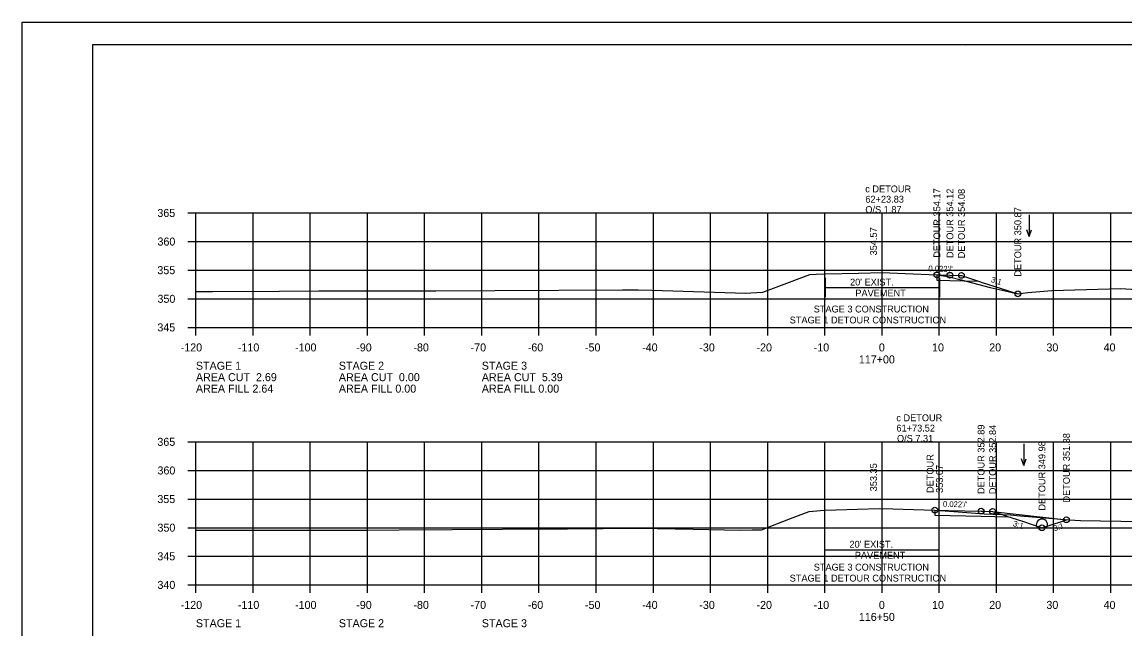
# Model space of a CAD drawing. Extents: x 1630712 to 1632516, y 782146 to 785403.
# Drawn here: x 1632182.6 to 1632375.4, y 785297.3 to 785403.3 of the extents above; entities that cross this region are included whole.
import ezdxf

# ---------------------------------------------------------------- set-up
doc = ezdxf.new("R2010")
doc.units = 0
for name, color, linetype in [('Default', 7, 'Continuous'), ('Notes', 7, 'Continuous'), ('R_Axis', 7, 'Continuous'), ('R_Axis Annot', 7, 'Continuous'), ('R_Border', 7, 'Continuous'), ('R_Detour Subgrade', 7, 'Continuous'), ('R_Detour Surface', 7, 'Continuous'), ('R_Exist Surface', 7, 'Continuous'), ('R_Grid', 7, 'Continuous'), ('R_No Plot', 7, 'Continuous'), ('R_Water Annot', 7, 'Continuous'), ('R_Xsect Elev', 7, 'Continuous'), ('R_Xsect Elev Detour', 7, 'Continuous'), ('R_Xsect Slope', 7, 'Continuous')]:
    doc.layers.add(name, color=color, linetype=linetype)

msp = doc.modelspace()

# ---------------------------------------------------------------- linework, layer by layer
at = {"layer": 'Default'}
for centre, radius, start, end in [((1632360.92, 785315.48), 0.995, 356.5785, 183.4215), ((1632360.34, 785315.45), 0.412, 183.4215, 256.4158), ((1632360.92, 785317.85), 2.89, 256.4158, 283.5842), ((1632361.5, 785315.45), 0.412, 283.5842, 356.5785)]:
    msp.add_arc(centre, radius, start, end, dxfattribs=at)
at = {"layer": 'Notes'}
for p, q in [((1632323.06, 785355.24), (1632323.06, 785358.64)), ((1632323.06, 785356.94), (1632343.06, 785356.94)), ((1632343.06, 785355.24), (1632343.06, 785358.64)), ((1632322.96, 785309.42), (1632322.96, 785312.82)), ((1632342.96, 785309.42), (1632342.96, 785312.82)), ((1632322.96, 785311.12), (1632342.96, 785311.12))]:
    msp.add_line(p, q, dxfattribs=at)
at = {"layer": 'R_Axis'}
for p, q in [((1632211.56, 785369.98), (1632212.96, 785369.98)), ((1632212.96, 785349.98), (1632212.96, 785369.98)), ((1632211.56, 785364.98), (1632212.96, 785364.98)), ((1632211.56, 785359.98), (1632212.96, 785359.98)), ((1632211.56, 785354.98), (1632212.96, 785354.98)), ((1632211.56, 785349.98), (1632212.96, 785349.98)), ((1632212.96, 785349.98), (1632492.96, 785349.98)), ((1632212.96, 785348.58), (1632212.96, 785349.98)), ((1632222.96, 785348.58), (1632222.96, 785349.98)), ((1632232.96, 785348.58), (1632232.96, 785349.98)), ((1632242.96, 785348.58), (1632242.96, 785349.98)), ((1632252.96, 785348.58), (1632252.96, 785349.98)), ((1632262.96, 785348.58), (1632262.96, 785349.98)), ((1632272.96, 785348.58), (1632272.96, 785349.98)), ((1632282.96, 785348.58), (1632282.96, 785349.98)), ((1632292.96, 785348.58), (1632292.96, 785349.98)), ((1632302.96, 785348.58), (1632302.96, 785349.98)), ((1632312.96, 785348.58), (1632312.96, 785349.98)), ((1632322.96, 785348.58), (1632322.96, 785349.98)), ((1632332.96, 785348.58), (1632332.96, 785349.98)), ((1632342.96, 785348.58), (1632342.96, 785349.98)), ((1632352.96, 785348.58), (1632352.96, 785349.98)), ((1632362.96, 785348.58), (1632362.96, 785349.98)), ((1632372.96, 785348.58), (1632372.96, 785349.98)), ((1632211.56, 785329.98), (1632212.96, 785329.98)), ((1632212.96, 785304.98), (1632212.96, 785329.98)), ((1632211.56, 785324.98), (1632212.96, 785324.98)), ((1632211.56, 785319.98), (1632212.96, 785319.98)), ((1632211.56, 785314.98), (1632212.96, 785314.98)), ((1632211.56, 785309.98), (1632212.96, 785309.98)), ((1632211.56, 785304.98), (1632212.96, 785304.98)), ((1632212.96, 785304.98), (1632492.96, 785304.98)), ((1632212.96, 785303.58), (1632212.96, 785304.98)), ((1632222.96, 785303.58), (1632222.96, 785304.98)), ((1632232.96, 785303.58), (1632232.96, 785304.98)), ((1632242.96, 785303.58), (1632242.96, 785304.98)), ((1632252.96, 785303.58), (1632252.96, 785304.98)), ((1632262.96, 785303.58), (1632262.96, 785304.98)), ((1632272.96, 785303.58), (1632272.96, 785304.98)), ((1632282.96, 785303.58), (1632282.96, 785304.98)), ((1632292.96, 785303.58), (1632292.96, 785304.98)), ((1632302.96, 785303.58), (1632302.96, 785304.98)), ((1632312.96, 785303.58), (1632312.96, 785304.98)), ((1632322.96, 785303.58), (1632322.96, 785304.98)), ((1632332.96, 785303.58), (1632332.96, 785304.98)), ((1632342.96, 785303.58), (1632342.96, 785304.98)), ((1632352.96, 785303.58), (1632352.96, 785304.98)), ((1632362.96, 785303.58), (1632362.96, 785304.98)), ((1632372.96, 785303.58), (1632372.96, 785304.98))]:
    msp.add_line(p, q, dxfattribs=at)
at = {"layer": 'R_Border'}
for p, q in [((1632194.96, 785399.44), (1632511.14, 785399.44)), ((1632194.96, 785193.98), (1632194.96, 785399.44)), ((1632347.48, 785399.18), (1632347.48, 785399.18)), ((1632347.48, 785399.18), (1632347.48, 785399.18))]:
    msp.add_line(p, q, dxfattribs=at)
at = {"layer": 'R_Detour Subgrade'}
for points in [[(1632342.55, 785359.15), (1632342.56, 785358.21), (1632344.83, 785358.16), (1632349.84, 785358.06)], [(1632342.55, 785359.15), (1632342.56, 785358.21), (1632344.83, 785358.16), (1632349.84, 785358.06)], [(1632342.18, 785318.05), (1632342.19, 785317.19), (1632350.27, 785317.01), (1632355.07, 785316.9)], [(1632342.18, 785318.05), (1632342.19, 785317.19), (1632350.27, 785317.01), (1632355.07, 785316.9)]]:
    msp.add_lwpolyline(points, dxfattribs=at)
at = {"layer": 'R_Detour Surface'}
msp.add_line((1632352.29, 785317.83), (1632365.2, 785316.37), dxfattribs=at)
for points in [[(1632342.55, 785359.15), (1632342.94, 785359.15), (1632344.83, 785359.1), (1632346.4, 785359.07), (1632346.84, 785359.06), (1632347.57, 785358.82), (1632349.84, 785358.06), (1632350.02, 785358), (1632350.45, 785357.85), (1632352.52, 785357.17), (1632356.7, 785355.85)], [(1632342.18, 785318.05), (1632344.57, 785318), (1632350.27, 785317.87), (1632350.91, 785317.86), (1632352.29, 785317.83), (1632353.79, 785317.33), (1632355.07, 785316.9), (1632355.35, 785316.81), (1632355.68, 785316.7), (1632357.54, 785316.09), (1632360.92, 785314.96), (1632364.33, 785316.08), (1632365.2, 785316.37)]]:
    msp.add_lwpolyline(points, dxfattribs=at)
at = {"layer": 'R_Exist Surface'}
for points in [[(1632212.96, 785356.27), (1632215.89, 785356.28), (1632227.56, 785356.32), (1632234.45, 785356.35), (1632239.66, 785356.35), (1632252.33, 785356.39), (1632254.92, 785356.39), (1632265.25, 785356.43), (1632287.58, 785356.55), (1632290.32, 785356.56), (1632292.68, 785356.48), (1632309.14, 785355.97), (1632309.99, 785356.02), (1632312.13, 785356.13), (1632314.93, 785357.18), (1632320.32, 785359.22), (1632321.42, 785359.26), (1632323.08, 785359.34), (1632328.86, 785359.48), (1632332.95, 785359.56), (1632337, 785359.38), (1632342.55, 785359.15), (1632343.27, 785359.05), (1632344.54, 785358.89), (1632346.78, 785358.29), (1632351.85, 785356.97), (1632355.04, 785356.24), (1632356.7, 785355.85), (1632358.47, 785356.06), (1632362.64, 785356.45), (1632372.74, 785356.7), (1632374.61, 785356.75), (1632377.59, 785356.62)], [(1632212.96, 785314.52), (1632213.37, 785314.52), (1632214.55, 785314.53), (1632227.97, 785314.54), (1632230.44, 785314.55), (1632242.78, 785314.57), (1632248.5, 785314.6), (1632257.79, 785314.66), (1632266.56, 785314.72), (1632277.92, 785314.76), (1632290.49, 785314.92), (1632299.91, 785314.73), (1632308.17, 785314.55), (1632310.25, 785314.59), (1632311.88, 785314.63), (1632316.94, 785316.57), (1632320.21, 785317.8), (1632322.22, 785317.96), (1632322.84, 785318.01), (1632324.88, 785318.08), (1632332.45, 785318.35), (1632334.85, 785318.28), (1632342.18, 785318.05), (1632344, 785317.91), (1632350.79, 785317.4), (1632355.42, 785317.2), (1632357.13, 785317.06), (1632365.68, 785316.33), (1632367.65, 785316.25), (1632378.23, 785316.07)]]:
    msp.add_lwpolyline(points, dxfattribs=at)
at = {"layer": 'R_Grid'}
for p, q in [((1632212.96, 785369.98), (1632492.96, 785369.98)), ((1632212.96, 785349.98), (1632212.96, 785369.98)), ((1632222.96, 785349.98), (1632222.96, 785369.98)), ((1632232.96, 785349.98), (1632232.96, 785369.98)), ((1632242.96, 785349.98), (1632242.96, 785369.98)), ((1632252.96, 785349.98), (1632252.96, 785369.98)), ((1632262.96, 785349.98), (1632262.96, 785369.98)), ((1632272.96, 785349.98), (1632272.96, 785369.98)), ((1632282.96, 785349.98), (1632282.96, 785369.98)), ((1632292.96, 785349.98), (1632292.96, 785369.98)), ((1632302.96, 785349.98), (1632302.96, 785369.98)), ((1632312.96, 785349.98), (1632312.96, 785369.98)), ((1632322.96, 785349.98), (1632322.96, 785369.98)), ((1632332.96, 785349.98), (1632332.96, 785369.98)), ((1632342.96, 785349.98), (1632342.96, 785369.98)), ((1632352.96, 785349.98), (1632352.96, 785369.98)), ((1632362.96, 785349.98), (1632362.96, 785369.98)), ((1632372.96, 785349.98), (1632372.96, 785369.98)), ((1632212.96, 785364.98), (1632492.96, 785364.98)), ((1632212.96, 785359.98), (1632492.96, 785359.98)), ((1632212.96, 785354.98), (1632492.96, 785354.98)), ((1632212.96, 785349.98), (1632492.96, 785349.98)), ((1632212.96, 785329.98), (1632492.96, 785329.98)), ((1632212.96, 785304.98), (1632212.96, 785329.98)), ((1632222.96, 785304.98), (1632222.96, 785329.98)), ((1632232.96, 785304.98), (1632232.96, 785329.98)), ((1632242.96, 785304.98), (1632242.96, 785329.98)), ((1632252.96, 785304.98), (1632252.96, 785329.98)), ((1632262.96, 785304.98), (1632262.96, 785329.98)), ((1632272.96, 785304.98), (1632272.96, 785329.98)), ((1632282.96, 785304.98), (1632282.96, 785329.98)), ((1632292.96, 785304.98), (1632292.96, 785329.98)), ((1632302.96, 785304.98), (1632302.96, 785329.98)), ((1632312.96, 785304.98), (1632312.96, 785329.98)), ((1632322.96, 785304.98), (1632322.96, 785329.98)), ((1632332.96, 785304.98), (1632332.96, 785329.98)), ((1632342.96, 785304.98), (1632342.96, 785329.98)), ((1632352.96, 785304.98), (1632352.96, 785329.98)), ((1632362.96, 785304.98), (1632362.96, 785329.98)), ((1632372.96, 785304.98), (1632372.96, 785329.98)), ((1632212.96, 785324.98), (1632492.96, 785324.98)), ((1632212.96, 785319.98), (1632492.96, 785319.98)), ((1632212.96, 785314.98), (1632492.96, 785314.98)), ((1632212.96, 785309.98), (1632492.96, 785309.98)), ((1632212.96, 785304.98), (1632492.96, 785304.98))]:
    msp.add_line(p, q, dxfattribs=at)
at = {"layer": 'R_No Plot'}
msp.add_line((1632182.56, 785403.34), (1632515.9, 785403.34), dxfattribs=at)
msp.add_lwpolyline([(1632182.56, 785403.34), (1632515.9, 785403.34), (1632515.9, 785190), (1632182.56, 785190)], close=True, dxfattribs=at)
for centre in [(1632342.55, 785359.15), (1632344.83, 785359.1), (1632346.84, 785359.06), (1632356.7, 785355.85), (1632356.7, 785355.85), (1632342.18, 785318.05), (1632350.27, 785317.87), (1632352.29, 785317.83), (1632365.2, 785316.37), (1632360.92, 785314.96)]:
    msp.add_circle(centre, 0.5, dxfattribs=at)
at = {"layer": 'R_Water Annot'}
for p, q in [((1632358.69, 785369.63), (1632358.69, 785365.86)), ((1632358.69, 785365.86), (1632358.27, 785367.02)), ((1632358.69, 785365.86), (1632359.11, 785367.02)), ((1632357.76, 785329.63), (1632357.76, 785325.86)), ((1632357.76, 785325.86), (1632357.34, 785327.02)), ((1632357.76, 785325.86), (1632358.18, 785327.02))]:
    msp.add_line(p, q, dxfattribs=at)

# ---------------------------------------------------------------- texts
at = {"layer": 'Notes'}
for s, p in [('c DETOUR', (1632330.02, 785373.58)), ('62+23.83', (1632330.04, 785371.78)), ('O/S 1.87', (1632330.03, 785369.98)), ("20' EXIST.", (1632327.36, 785357.3)), ('PAVEMENT', (1632328.29, 785355.38)), ('STAGE 3 CONSTRUCTION', (1632321.01, 785352.59)), ('STAGE 1 DETOUR CONSTRUCTION', (1632316.81, 785350.67)), ('c DETOUR', (1632335.46, 785333.58)), ('61+73.52', (1632335.47, 785331.78)), ('O/S 7.31', (1632335.57, 785329.98)), ("20' EXIST.", (1632327.26, 785311.48)), ('PAVEMENT', (1632328.19, 785309.56)), ('STAGE 3 CONSTRUCTION', (1632321.01, 785307.48)), ('STAGE 1 DETOUR CONSTRUCTION', (1632316.81, 785305.56))]:
    msp.add_text(s, height=1.2, dxfattribs=at).set_placement(p)
at = {"layer": 'R_Axis'}
for p in [(1632212.96, 785349.98), (1632212.96, 785304.98)]:
    msp.add_text('-', height=0.0001, dxfattribs=at).set_placement(p)
at = {"layer": 'R_Axis Annot'}
for s, p in [('365', (1632206.22, 785369.28)), ('360', (1632206.24, 785364.28)), ('355', (1632206.22, 785359.28)), ('350', (1632206.24, 785354.28)), ('345', (1632206.22, 785349.28)), ('-120', (1632210.3, 785345.78)), ('-110', (1632220.3, 785345.78)), ('-100', (1632230.3, 785345.78)), ('-90', (1632241, 785345.78)), ('-80', (1632251, 785345.78)), ('-70', (1632261, 785345.78)), ('-60', (1632271, 785345.78)), ('-50', (1632281, 785345.78)), ('-40', (1632291, 785345.78)), ('-30', (1632301, 785345.78)), ('-20', (1632311, 785345.78)), ('-10', (1632321, 785345.78)), ('0', (1632332.4, 785345.78)), ('10', (1632341.7, 785345.78)), ('20', (1632351.7, 785345.78)), ('30', (1632361.7, 785345.78)), ('40', (1632371.7, 785345.78)), ('STAGE 1', (1632212.96, 785342.58)), ('STAGE 2', (1632237.96, 785342.58)), ('STAGE 3', (1632262.96, 785342.58)), ('117+00', (1632328.9, 785343.68)), ('AREA CUT  2.69', (1632212.96, 785340.58)), ('AREA CUT  0.00', (1632237.96, 785340.58)), ('AREA CUT  5.39', (1632262.96, 785340.58)), ('AREA FILL 2.64', (1632212.96, 785338.58)), ('AREA FILL 0.00', (1632237.96, 785338.58)), ('AREA FILL 0.00', (1632262.96, 785338.58)), ('365', (1632206.22, 785329.28)), ('360', (1632206.24, 785324.28)), ('355', (1632206.22, 785319.28)), ('350', (1632206.24, 785314.28)), ('345', (1632206.22, 785309.28)), ('340', (1632206.24, 785304.28)), ('-120', (1632210.3, 785300.78)), ('-110', (1632220.3, 785300.78)), ('-100', (1632230.3, 785300.78)), ('-90', (1632241, 785300.78)), ('-80', (1632251, 785300.78)), ('-70', (1632261, 785300.78)), ('-60', (1632271, 785300.78)), ('-50', (1632281, 785300.78)), ('-40', (1632291, 785300.78)), ('-30', (1632301, 785300.78)), ('-20', (1632311, 785300.78)), ('-10', (1632321, 785300.78)), ('0', (1632332.4, 785300.78)), ('10', (1632341.7, 785300.78)), ('20', (1632351.7, 785300.78)), ('30', (1632361.7, 785300.78)), ('40', (1632371.7, 785300.78)), ('STAGE 1', (1632212.96, 785297.58)), ('STAGE 2', (1632237.96, 785297.58)), ('STAGE 3', (1632262.96, 785297.58)), ('116+50', (1632328.9, 785298.68))]:
    msp.add_text(s, height=1.4, dxfattribs=at).set_placement(p)
at = {"layer": 'R_Xsect Elev'}
for s, p in [('354.57', (1632332.06, 785362.56)), ('353.35', (1632332.06, 785321.33))]:
    msp.add_text(s, height=1.2, rotation=90, dxfattribs=at).set_placement(p)
at = {"layer": 'R_Xsect Elev Detour'}
for s, p in [('DETOUR 354.17', (1632343.15, 785362.15)), ('DETOUR 354.12', (1632345.43, 785362.1)), ('DETOUR 354.08', (1632347.44, 785362.06)), ('DETOUR 350.87', (1632357.3, 785358.85)), ('DETOUR 352.89', (1632350.87, 785320.87)), ('DETOUR 352.84', (1632352.89, 785320.83)), ('DETOUR 349.98', (1632361.52, 785317.96)), ('DETOUR 351.38', (1632365.8, 785319.37)), ('DETOUR', (1632341.96, 785321.05)), ('353.07', (1632343.61, 785321.05))]:
    msp.add_text(s, height=1.2, rotation=90, dxfattribs=at).set_placement(p)
at = {"layer": 'R_Xsect Slope'}
for s, rotation, p in [("0.022'/'", 358.7545, (1632341.06, 785359.79)), ('3:1', 341.9578, (1632351.92, 785357.93)), ("0.022'/'", 358.7458, (1632343.6, 785318.62)), ('3:1', 341.6337, (1632355.76, 785315.29)), ('3:1', 18.1411, (1632363.09, 785314.33))]:
    msp.add_text(s, height=1, rotation=rotation, dxfattribs=at).set_placement(p)

doc.saveas('drawing.dxf')
